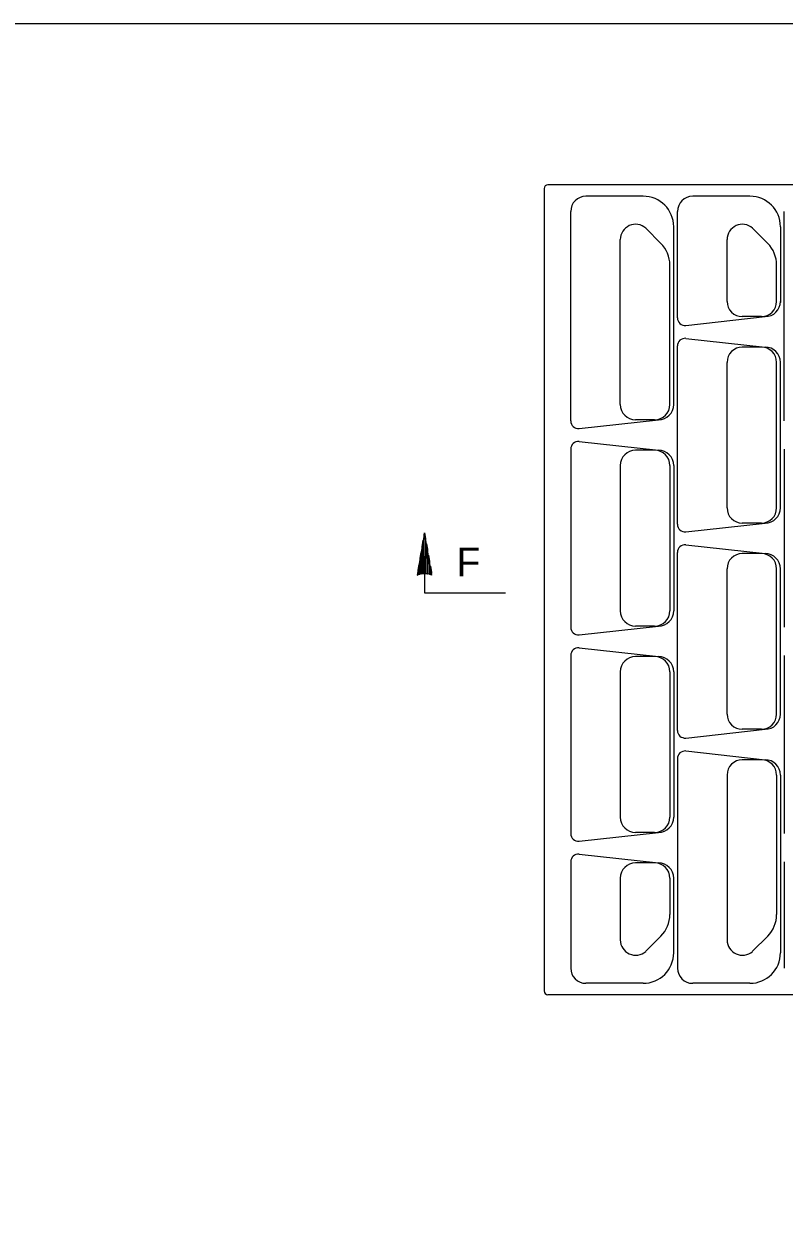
# Model space of a CAD drawing. Extents: x 2087776 to 2104538, y 970919 to 982612.
# Drawn here: x 2097412 to 2097800, y 978060 to 978665 of the extents above; entities that cross this region are included whole.
import ezdxf

# ---------------------------------------------------------------- set-up
doc = ezdxf.new("R2010")
doc.units = 0
doc.layers.add('1', color=7, linetype='Continuous')

msp = doc.modelspace()

# ---------------------------------------------------------------- linework, layer by layer
at = {"layer": '1'}
for p, q in [((2098046.75, 978583.27), (2097679.3, 978583.27)), ((2097677.36, 978581.32), (2097677.36, 978172.07)), ((2097727.91, 978577.43), (2097698.74, 978577.43)), ((2097782.34, 978577.43), (2097753.18, 978577.43)), ((2097690.97, 978462.81), (2097690.97, 978569.66)), ((2097745.4, 978515.43), (2097745.4, 978569.66)), ((2097799.84, 978462.81), (2097799.84, 978569.66)), ((2097736.96, 978553.36), (2097729.2, 978561.12)), ((2097743.46, 978471.18), (2097743.46, 978561.88)), ((2097791.4, 978553.36), (2097783.64, 978561.12)), ((2097797.9, 978561.88), (2097797.9, 978523.3)), ((2097716.24, 978471.18), (2097716.24, 978555.32)), ((2097770.68, 978523.8), (2097770.68, 978555.32)), ((2097741.51, 978471.18), (2097741.51, 978542.36)), ((2097795.95, 978523.8), (2097795.95, 978542.36)), ((2097749.65, 978511.56), (2097790.12, 978516.03)), ((2097788.17, 978516.03), (2097778.45, 978516.03)), ((2097749.65, 978504.94), (2097790.12, 978500.47)), ((2097745.4, 978410.11), (2097745.4, 978501.07)), ((2097788.17, 978500.47), (2097778.45, 978500.47)), ((2097770.68, 978418.48), (2097770.68, 978492.69)), ((2097795.95, 978418.48), (2097795.95, 978492.69)), ((2097797.9, 978418.48), (2097797.9, 978492.69)), ((2097695.21, 978458.94), (2097735.68, 978463.4)), ((2097733.74, 978463.4), (2097724.02, 978463.4)), ((2097695.21, 978452.32), (2097735.68, 978447.85)), ((2097690.97, 978448.44), (2097690.97, 978357.57)), ((2097733.74, 978447.85), (2097724.02, 978447.85)), ((2097799.84, 978448.44), (2097799.84, 978357.57)), ((2097716.24, 978440.07), (2097716.24, 978365.94)), ((2097741.51, 978440.07), (2097741.51, 978365.94)), ((2097743.46, 978440.07), (2097743.46, 978365.94)), ((2097749.65, 978406.24), (2097790.12, 978410.7)), ((2097788.17, 978410.7), (2097778.45, 978410.7)), ((2097745.4, 978304.95), (2097745.4, 978395.75)), ((2097749.65, 978399.62), (2097790.12, 978395.15)), ((2097788.17, 978395.15), (2097778.45, 978395.15)), ((2097616.41, 978384.94), (2097616.41, 978375.07)), ((2097770.68, 978313.32), (2097770.68, 978387.37)), ((2097795.95, 978313.32), (2097795.95, 978387.37)), ((2097797.9, 978313.32), (2097797.9, 978387.37)), ((2097616.41, 978375.07), (2097657.64, 978375.07)), ((2097695.21, 978353.7), (2097735.68, 978358.16)), ((2097733.74, 978358.16), (2097724.02, 978358.16)), ((2097695.21, 978347.08), (2097735.68, 978342.61)), ((2097690.97, 978343.21), (2097690.97, 978252.33)), ((2097733.74, 978342.61), (2097724.02, 978342.61)), ((2097799.84, 978343.21), (2097799.84, 978252.33)), ((2097716.24, 978334.83), (2097716.24, 978260.7)), ((2097741.51, 978334.83), (2097741.51, 978260.7)), ((2097743.46, 978334.83), (2097743.46, 978260.7)), ((2097749.65, 978301.08), (2097790.12, 978305.54)), ((2097788.17, 978305.54), (2097778.45, 978305.54)), ((2097749.65, 978294.46), (2097790.12, 978289.99)), ((2097745.4, 978290.59), (2097745.4, 978183.74)), ((2097788.17, 978289.99), (2097778.45, 978289.99)), ((2097770.68, 978282.21), (2097770.68, 978198.07)), ((2097795.95, 978282.21), (2097795.95, 978211.03)), ((2097797.9, 978282.21), (2097797.9, 978191.51)), ((2097695.21, 978248.45), (2097735.68, 978252.92)), ((2097733.74, 978252.92), (2097724.02, 978252.92)), ((2097690.97, 978237.96), (2097690.97, 978183.74)), ((2097695.21, 978241.84), (2097735.68, 978237.37)), ((2097799.84, 978237.96), (2097799.84, 978183.74)), ((2097733.74, 978237.37), (2097724.02, 978237.37)), ((2097716.24, 978229.59), (2097716.24, 978198.07)), ((2097741.51, 978229.59), (2097741.51, 978211.03)), ((2097743.46, 978191.51), (2097743.46, 978229.59)), ((2097736.96, 978200.03), (2097729.2, 978192.28)), ((2097791.4, 978200.03), (2097783.64, 978192.28)), ((2097727.91, 978175.96), (2097698.74, 978175.96)), ((2097782.34, 978175.96), (2097753.18, 978175.96)), ((2098046.75, 978170.13), (2097679.3, 978170.13))]:
    msp.add_line(p, q, dxfattribs=at)
for points in [[(2098759.93, 976815.01), (2098759.93, 978665.4), (2096181.19, 978665.4), (2096181.19, 976815.01), (2098759.93, 976815.01), (2098759.93, 976901.49), (2098103.76, 976901.49), (2098103.76, 977113.68), (2098759.93, 977113.68), (2098759.93, 977208.71), (2098103.76, 977208.71), (2098103.76, 976815.01), (2098362.29, 976815.01), (2098362.29, 976901.49), (2098362.29, 976815.01), (2098614.92, 976815.01), (2098614.92, 976901.49), (2098614.92, 976861.08), (2098759.93, 976861.08)], [(2097620.22, 978384.21), (2097616.41, 978405.71), (2097612.72, 978384.21), (2097613.2, 978384.45), (2097613.14, 978386.73), (2097613.63, 978389.51), (2097613.68, 978384.61), (2097614.18, 978384.7), (2097614.21, 978392.86), (2097614.7, 978395.74), (2097614.68, 978384.83), (2097615.22, 978384.94), (2097615.21, 978398.68), (2097615.77, 978401.96), (2097615.75, 978385), (2097616.23, 978384.98), (2097616.25, 978404.73), (2097616.42, 978405.67), (2097616.9, 978402.93), (2097616.77, 978385.03), (2097617.27, 978384.96), (2097617.39, 978400.18), (2097617.87, 978397.46), (2097617.87, 978384.87), (2097618.33, 978384.86), (2097618.42, 978394.39), (2097618.96, 978391.28), (2097618.91, 978384.7), (2097619.45, 978384.56), (2097619.42, 978388.72), (2097619.97, 978385.57), (2097619.86, 978384.37)]]:
    msp.add_lwpolyline(points, dxfattribs=at)
for centre, radius, start, end in [((2097679.3, 978581.32), 1.94, 90, 180), ((2097698.74, 978569.66), 7.78, 90, 180), ((2097727.91, 978561.88), 15.55, 0, 90), ((2097753.18, 978569.66), 7.78, 90, 180), ((2097782.34, 978561.88), 15.55, 0, 90), ((2097724.02, 978555.32), 7.78, 48.18441, 180), ((2097778.45, 978555.32), 7.78, 48.18441, 180), ((2097725.96, 978542.36), 15.55, 0, 45), ((2097780.4, 978542.36), 15.55, 0, 45), ((2097778.45, 978523.8), 7.78, 180, 270), ((2097788.17, 978523.8), 7.78, 270, 0), ((2097790.12, 978523.8), 7.78, 270, 0), ((2097749.29, 978515.43), 3.89, 180, 275.29008), ((2097749.29, 978501.07), 3.89, 84.70992, 180), ((2097778.45, 978492.69), 7.78, 90, 180), ((2097788.17, 978492.69), 7.78, 0, 90), ((2097790.12, 978492.69), 7.78, 0, 90), ((2097724.02, 978471.18), 7.78, 180, 270), ((2097733.74, 978471.18), 7.78, 270, 0), ((2097735.68, 978471.18), 7.78, 270, 0), ((2097694.85, 978462.81), 3.89, 180, 275.29008), ((2097694.85, 978448.44), 3.89, 84.70992, 180), ((2097724.02, 978440.07), 7.78, 90, 180), ((2097733.74, 978440.07), 7.78, 0, 90), ((2097735.68, 978440.07), 7.78, 0, 90), ((2097778.45, 978418.48), 7.78, 180, 270), ((2097788.17, 978418.48), 7.78, 270, 0), ((2097790.12, 978418.48), 7.78, 270, 0), ((2097749.29, 978410.11), 3.89, 180, 275.29008), ((2097749.29, 978395.75), 3.89, 84.70992, 180), ((2097778.45, 978387.37), 7.78, 90, 180), ((2097788.17, 978387.37), 7.78, 0, 90), ((2097790.12, 978387.37), 7.78, 0, 90), ((2097616.46, 978374.99), 9.95, 67.87619, 112.12381), ((2097724.02, 978365.94), 7.78, 180, 270), ((2097733.74, 978365.94), 7.78, 270, 0), ((2097735.68, 978365.94), 7.78, 270, 0), ((2097694.85, 978357.57), 3.89, 180, 275.29008), ((2097694.85, 978343.21), 3.89, 84.70992, 180), ((2097724.02, 978334.83), 7.78, 90, 180), ((2097733.74, 978334.83), 7.78, 0, 90), ((2097735.68, 978334.83), 7.78, 0, 90), ((2097778.45, 978313.32), 7.78, 180, 270), ((2097788.17, 978313.32), 7.78, 270, 0), ((2097790.12, 978313.32), 7.78, 270, 0), ((2097749.29, 978304.95), 3.89, 180, 275.29008), ((2097749.29, 978290.59), 3.89, 84.70992, 180), ((2097778.45, 978282.21), 7.78, 90, 180), ((2097788.17, 978282.21), 7.78, 0, 90), ((2097790.12, 978282.21), 7.78, 0, 90), ((2097724.02, 978260.7), 7.78, 180, 270), ((2097733.74, 978260.7), 7.78, 270, 0), ((2097735.68, 978260.7), 7.78, 270, 0), ((2097694.85, 978252.33), 3.89, 180, 275.29008), ((2097694.85, 978237.96), 3.89, 84.70992, 180), ((2097724.02, 978229.59), 7.78, 90, 180), ((2097733.74, 978229.59), 7.78, 0, 90), ((2097735.68, 978229.59), 7.78, 0, 90), ((2097725.96, 978211.03), 15.55, 315, 0), ((2097780.4, 978211.03), 15.55, 315, 0), ((2097724.02, 978198.07), 7.78, 180, 311.81559), ((2097778.45, 978198.07), 7.78, 180, 311.81559), ((2097727.91, 978191.51), 15.55, 270, 0), ((2097782.34, 978191.51), 15.55, 270, 0), ((2097698.74, 978183.74), 7.78, 180, 270), ((2097753.18, 978183.74), 7.78, 180, 270), ((2097679.3, 978172.07), 1.94, 180, 270)]:
    msp.add_arc(centre, radius, start, end, dxfattribs=at)

# ---------------------------------------------------------------- texts
msp.add_text('F', height=14.76, dxfattribs=at).set_placement((2097632.77, 978383.47))

doc.saveas('drawing.dxf')
